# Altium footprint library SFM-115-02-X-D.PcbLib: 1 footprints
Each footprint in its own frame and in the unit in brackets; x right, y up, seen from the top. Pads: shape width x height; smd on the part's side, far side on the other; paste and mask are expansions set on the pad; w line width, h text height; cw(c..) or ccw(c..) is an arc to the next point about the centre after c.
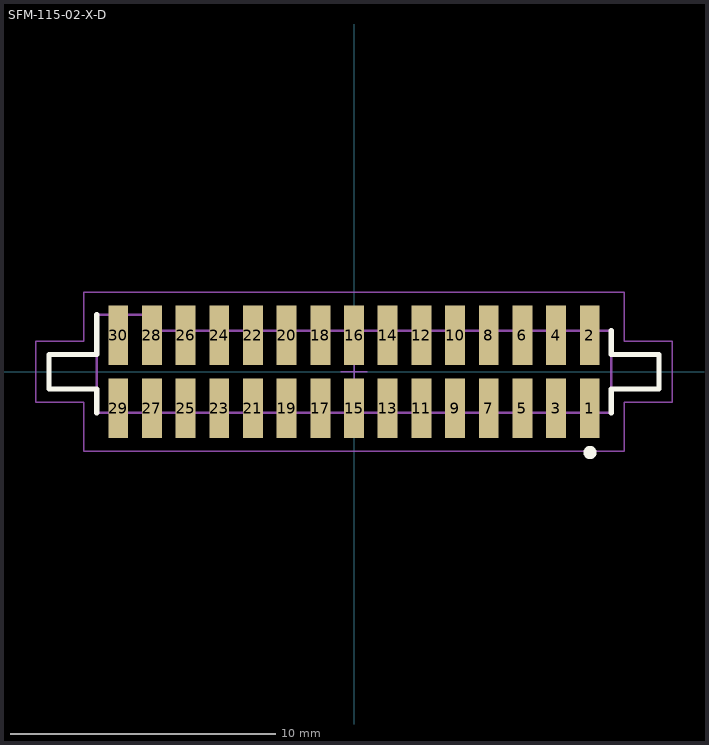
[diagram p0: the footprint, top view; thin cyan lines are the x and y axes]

## SFM-115-02-X-D [mm] "1.27mm pitch, 30 pin, socket strip; SMT"
height 4.57
pads (30):
  rect 0.75x2.25 smd mask+0: 1(8.89,-1.375) 2(8.89,1.375) 3(7.62,-1.375) 4(7.62,1.375) 5(6.35,-1.375) 6(6.35,1.375) 7(5.08,-1.375) 8(5.08,1.375) 9(3.81,-1.375) 10(3.81,1.375) 11(2.54,-1.375) 12(2.54,1.375) 13(1.27,-1.375) 14(1.27,1.375) 15(0,-1.375) 16(0,1.375) 17(-1.27,-1.375) 18(-1.27,1.375) 19(-2.54,-1.375) 20(-2.54,1.375) 21(-3.81,-1.375) 22(-3.81,1.375) 23(-5.08,-1.375) 24(-5.08,1.375) 25(-6.35,-1.375) 26(-6.35,1.375) 27(-7.62,-1.375) 28(-7.62,1.375) 29(-8.89,-1.375) 30(-8.89,1.375)
Top Overlay:
  circle w0.25: c8.9,-3.05 r0.125
  lines w0.2: -9.7,-1.55 -9.7,-0.65 -11.5,-0.65 -11.5,0.65 -9.7,0.65 -9.7,2.15 ; 9.7,-1.55 9.7,-0.65 11.5,-0.65 11.5,0.65 9.7,0.65 9.7,1.55
Mechanical 12:
  lines w0.001: -11.5,-0.65 -11.5,0.65 -9.7,0.65 -9.7,2.15 -7.65,2.15 -7.65,1.55 9.7,1.55 9.7,0.65 11.5,0.65 11.5,-0.65 9.7,-0.65 9.7,-1.55 -9.7,-1.55 -9.7,-0.65 -11.5,-0.65
Mechanical 13:
  lines w0.1: -9.7,-0.65 -11.5,-0.65 -11.5,0.65 -9.7,0.65 ; -9.7,-0.65 -9.7,-1.55 9.7,-1.55 9.7,-0.65 ; -9.7,-0.65 -9.7,0.65 ; -9.7,0.65 -9.7,2.15 -7.65,2.15 -7.65,1.55 9.7,1.55 9.7,0.65 ; 9.7,-0.65 11.5,-0.65 11.5,0.65 9.7,0.65 ; 9.7,-0.65 9.7,0.65
  text ".Designator" at 0,-0.127 h1.52
Mechanical 15:
  lines w0.05: -0.5,0 0.5,0 ; 0,-0.5 0,0.5 ; -12,-1.15 -10.2,-1.15 -10.2,-3 10.2,-3 10.2,-1.15 12,-1.15 12,1.15 10.2,1.15 10.2,3 -10.2,3 -10.2,1.15 -12,1.15 -12,-1.15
